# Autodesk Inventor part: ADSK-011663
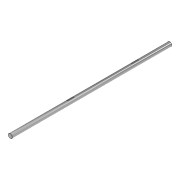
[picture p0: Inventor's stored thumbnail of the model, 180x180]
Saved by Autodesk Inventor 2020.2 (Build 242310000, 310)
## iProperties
Created: 2000-02
Part Number: ADSK-011663
Material: Pearson CRS
Document SubType Name: Modeling
Description: SHFT2K,TH,BX,07-06,288,SIDE RAIL ADJUST,RH
Designer: sspink
Density: 7.83 g/cm^3
Appearance: Chrom - poliert
Mass: 1796.76 g
Surface Area: 467.119 cm^2
Volume: 229.471 cm^3
Control State: 0
Checked Out: False
Master: False
Shininess: 60.0
Length Units: 11269
Angle Units: 11279
Time Units: 11290
Mass Units: 11283
Length Display Precision: 3
Angle Display Precision: 2
Compacted: True
Cutlength: 28.81
Material Desc: THREADED-ROD,0.750-06ACME RH
Material_Number: A084661
Dimensions: 20x732x20 mm
Mass: 1,797 kg
VLT_Material: Pearson CRS
Density: 7.83
Volumn: 260.62499187379797
Area: 552.9445365651443
PropertySet Name: Model Information
Author: sspink
Revision Number: -
Title: SHFT2K,TH,BX,07-06,288,SIDE RAIL ADJUST,RH
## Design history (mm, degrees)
node "Solide1"
  node "Extrusion1" dims "d1" = 732, "d2" = 0
  node "Extrusion2" dims "d7" = 32, "d8" = 0
  node "Extrusion3" dims "d10" = 32, "d11" = 0
  node "Chamfer1" dims "d13" = 1, "d14" = 1, "d15" = 45 deg
sketch "Sketch1"
  geometry: C1 r 10 at (0, 0); 1 further point
  constraints: 1 centre point, 1 coincident
  dimensions: "d0" = 20 diameter of C1
workplane "Work Plane1"
sketch "Sketch2"
  geometry: L1 (-14, 0)-(14, 0) reference; L2 (0, 0)-(0, 8.5); L3 (0, 8.5)-(2.5, 8.5); L4 (0, 8.5)-(2.5, 8.5); L5 (0, 8.5)-(2.5, 8.5); L6 (0, 8.5)-(-2.5, 8.5); L7 (-2.5, 8.5)-(-2.5, 9.682); L8 (2.5, 8.5)-(2.5, 9.682); A1 r 10 centre (0, 0) between (-2.5, 9.682) and (2.5, 9.682) reference
  constraints: 14 end point, 4 equal length, 3 perpendicular, 2 point on circle
  dimensions: "d5" = 5 distance between parallel lines of L8 L7; "d6" = 2.5 distance between parallel lines of L2 L7 (= 0.5 x d5); "d12" = 18.5 dimension on A1 L6
fillet "Rundung4"
workplane "Work Plane2"
sketch "Sketch3"
  geometry: L1 (-2.5, 8.5)-(2.5, 8.5) reference; L2 (-2.5, 9.682)-(-2.5, 8.5) reference; L3 (2.5, 8.5)-(2.5, 9.682) reference; C1 r 10 at (0, 0) reference; A1 r 10 centre (0, 0) between (2.5, 9.682) and (-2.5, 9.682) reference; 2 further points
  node "Projizierte Kontur1"
fillet "Rundung1"
fillet "Rundung2"
fillet "Rundung3"
node "Corps solides"
node "Corps surfaciques"
other parameters: "d9" = -295
